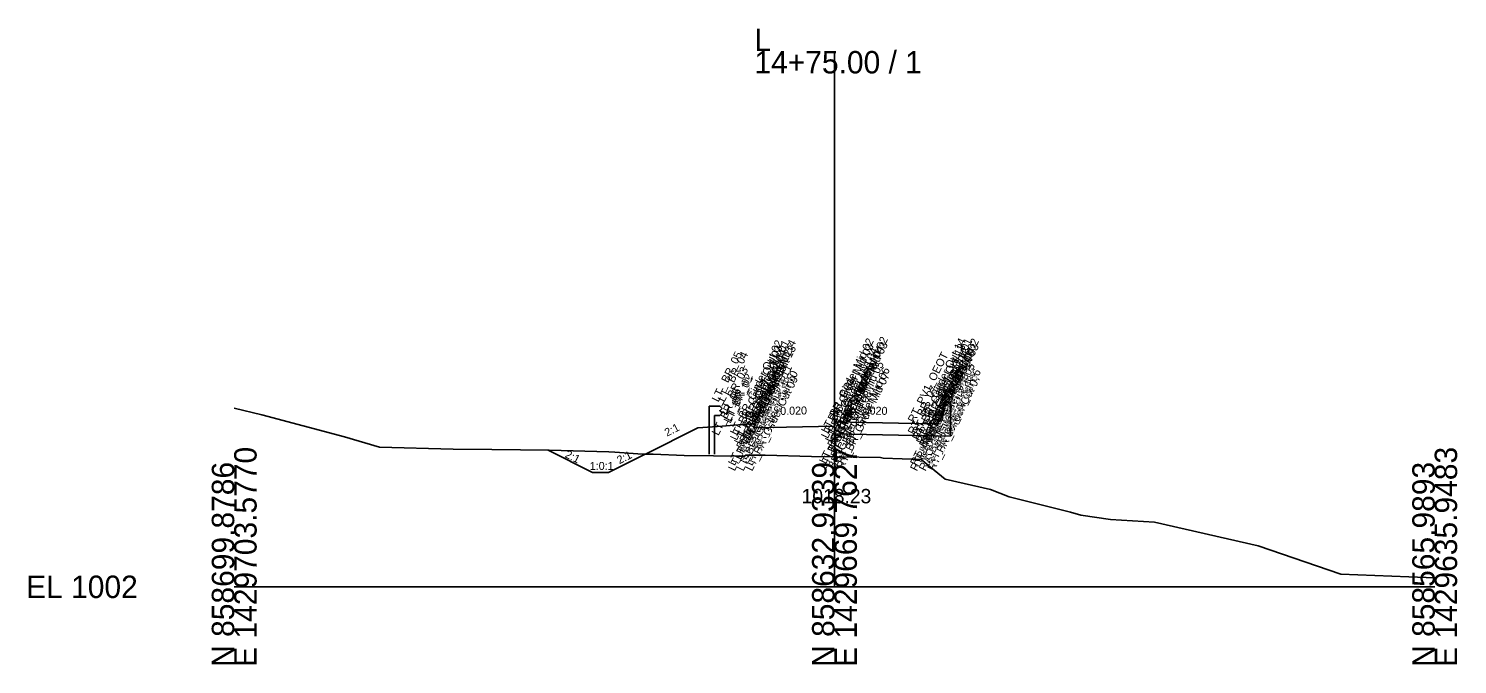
# Model space of a CAD drawing. Extents: x -26 to 176, y -10 to 13058.
# Drawn here: x -25.7 to 152.8, y 6490.3 to 6569.7 of the extents above; entities that cross this region are included whole.
import ezdxf

# ---------------------------------------------------------------- set-up
doc = ezdxf.new("R2010")
doc.units = 0
for name, color, linetype in [('Default', 7, 'Continuous'), ('Exist Cross Section Cell', 7, 'Continuous'), ('Exist XS Center Line Elevation Label', 7, 'Continuous'), ('Exist XS Ground Line', 7, 'Continuous'), ('Old_Level_50', 7, 'Continuous'), ('Prop CMT Concrete Structures', 7, 'Continuous'), ('Prop CMT Guardrail Graphics', 7, 'Continuous'), ('Prop CMT Pvmt Course 1', 7, 'Continuous'), ('Prop CMT Pvmt Surface Shoulder', 7, 'Continuous'), ('Prop CMT Shld Paved Course 1', 7, 'Continuous'), ('Prop CMT Slope Grass', 7, 'Continuous'), ('Prop CMT Subgrade Earthwork', 7, 'Continuous'), ('Prop XS Dump Level', 7, 'Continuous'), ('Prop XS SE Text', 7, 'Continuous'), ('Prop XS Side Slope Text', 7, 'Continuous')]:
    doc.layers.add(name, color=color, linetype=linetype)

msp = doc.modelspace()

# ---------------------------------------------------------------- linework, layer by layer
at = {"layer": 'Exist Cross Section Cell'}
for p, q in [((75, 6500), (75, 6566.93)), ((0, 6500), (75, 6500)), ((75, 6500), (150, 6500))]:
    msp.add_line(p, q, dxfattribs=at)
at = {"layer": 'Exist XS Ground Line'}
msp.add_lwpolyline([(0, 6522.31), (3.44, 6521.49), (13.79, 6518.72), (18.17, 6517.45), (27.35, 6517.18), (32.2, 6517.15), (39.36, 6517.05), (46.79, 6516.88), (47.56, 6516.84), (51.03, 6516.57), (52.33, 6516.56), (56.24, 6516.42), (59.9, 6516.38), (62.96, 6516.34), (63.78, 6516.33), (63.92, 6516.46), (66.35, 6516.43), (72.14, 6516.29), (75, 6516.23), (75.38, 6516.22), (80.77, 6516.15), (81.07, 6516.09), (85.84, 6515.89), (88.82, 6513.45), (94.51, 6512.15), (96.84, 6511.22), (104.48, 6509.34), (105.79, 6508.93), (109.51, 6508.39), (114.97, 6508.07), (127.95, 6505.12), (138.29, 6501.59), (146.77, 6501.25), (150, 6501.11)], dxfattribs=at)
at = {"layer": 'Old_Level_50'}
for points in [[(63.78, 6516.33), (63.92, 6516.46), (66.35, 6516.43), (72.14, 6516.29), (75, 6516.23), (75, 6520.07), (65, 6519.87), (65, 6520.41), (60.95, 6520.08), (57.95, 6519.84), (51.39, 6516.57), (52.33, 6516.56), (56.24, 6516.42), (59.9, 6516.38), (62.96, 6516.34)], [(51.39, 6516.57), (52.33, 6516.56), (56.24, 6516.42), (59.9, 6516.38), (62.96, 6516.34), (63.78, 6516.33), (63.92, 6516.46), (66.35, 6516.43), (72.14, 6516.29), (75, 6516.23), (75, 6520.07), (65, 6519.87), (65, 6520.41), (60.95, 6520.08), (57.95, 6519.84)], [(51.03, 6516.57), (51.37, 6516.57), (46.78, 6514.27), (44.78, 6514.27), (39.22, 6517.05), (39.36, 6517.05), (46.79, 6516.88), (47.56, 6516.84)], [(51.03, 6516.57), (51.37, 6516.57), (46.78, 6514.27), (44.78, 6514.27), (39.22, 6517.05), (39.36, 6517.05), (46.79, 6516.88), (47.56, 6516.84)]]:
    msp.add_lwpolyline(points, close=True, dxfattribs=at)
at = {"layer": 'Prop CMT Concrete Structures'}
for points in [[(75, 6520.61), (85, 6520.41), (88, 6520.35), (88.01, 6520.6), (88.59, 6521.43), (88.76, 6523.01), (89.5, 6523.01), (89.5, 6518.82)], [(75, 6519.11), (75, 6520.61)], [(75, 6519.11), (75, 6520.61)], [(89.5, 6518.82), (85, 6518.91), (75, 6519.11)]]:
    msp.add_lwpolyline(points, dxfattribs=at)
at = {"layer": 'Prop CMT Guardrail Graphics'}
for points in [[(59.34, 6516.58), (59.34, 6522.58)], [(59.34, 6522.58), (60.68, 6522.58), (60.95, 6522.29)], [(60.95, 6522.29), (60.68, 6522)], [(60.68, 6522), (60.95, 6521.71)], [(60.95, 6521.71), (60.68, 6521.42), (60.01, 6521.42)], [(60.01, 6521.42), (60.01, 6516.58)]]:
    msp.add_lwpolyline(points, dxfattribs=at)
at = {"layer": 'Prop CMT Pvmt Course 1'}
for points in [[(65, 6520.41), (65, 6519.87)], [(75, 6516.23), (75, 6520.07)]]:
    msp.add_lwpolyline(points, dxfattribs=at)
at = {"layer": 'Prop CMT Pvmt Surface Shoulder'}
msp.add_lwpolyline([(65, 6520.41), (65, 6520.41)], dxfattribs=at)
at = {"layer": 'Prop CMT Shld Paved Course 1'}
for points in [[(65, 6520.41), (65, 6520.41)], [(65, 6519.87), (65, 6520.41)]]:
    msp.add_lwpolyline(points, dxfattribs=at)
at = {"layer": 'Prop CMT Slope Grass'}
for p, q in [((44.78, 6514.27), (39.22, 6517.05)), ((46.78, 6514.27), (51.37, 6516.57)), ((46.78, 6514.27), (44.78, 6514.27))]:
    msp.add_line(p, q, dxfattribs=at)
for points in [[(60.95, 6520.08), (57.95, 6519.84)], [(65, 6520.41), (60.95, 6520.08)], [(57.95, 6519.84), (51.39, 6516.57)]]:
    msp.add_lwpolyline(points, dxfattribs=at)
at = {"layer": 'Prop CMT Subgrade Earthwork'}
msp.add_lwpolyline([(75, 6520.07), (65, 6519.87)], dxfattribs=at)

# ---------------------------------------------------------------- texts
at = {"layer": 'Default'}
msp.add_text('-', height=0.0001, dxfattribs=at).set_placement((0, 6500))
at = {"layer": 'Exist Cross Section Cell'}
for s, p in [('L', (65, 6566.93)), ('14+75.00 / 1', (65, 6564.13)), ('EL 1002', (-26, 6498.6))]:
    msp.add_text(s, height=2.8, dxfattribs=at).set_placement(p)
for s, p in [('E 1429703.5770', (2.8, 6490)), ('E 1429669.7627', (77.8, 6490)), ('E 1429635.9483', (152.8, 6490)), ('N 858699.8786', (0, 6490)), ('N 858632.9339', (75, 6490)), ('N 858565.9893', (150, 6490))]:
    msp.add_text(s, height=2.8, rotation=90, dxfattribs=at).set_placement(p)
at = {"layer": 'Exist XS Center Line Elevation Label'}
msp.add_text('1018.23', height=1.8, dxfattribs=at).set_placement((70.9, 6510.43))
msp.add_text('1018.23', height=1.8, dxfattribs=at).set_placement((70.9, 6510.43))
msp.add_text('1018.23', height=1.8, dxfattribs=at).set_placement((70.9, 6510.43))
at = {"layer": 'Prop XS Dump Level'}
for s, p in [('LT_BR_Girder Out 02', (62.79, 6518.86)), ('LT_BR_Girder Out 14', (64.46, 6518.9)), ('LT_BR_Girder Mid 02', (74.17, 6519.09)), ('RT_BR_Girder Mid 02', (75.83, 6519.09)), ('RT_BR_Girder Out 14', (85.54, 6518.9)), ('RT_BR_Girder Out 01', (86.38, 6518.88)), ('RT_BR_Girder Out 02', (87.21, 6518.86)), ('LT_ BR_05', (60.5, 6523.01)), ('LT_ BR_04', (61.24, 6523.01)), ('LT_BR_Girder Out 03', (62.79, 6518.21)), ('LT_BR_Girder Out 04', (63.29, 6517.71)), ('LT_BR_Girder Out 01', (63.62, 6518.88)), ('LT_BR_Girder Out 12', (63.96, 6517.71)), ('LT_BR_Girder Out 13', (64.46, 6518.21)), ('LT_PV1_OEOT', (65, 6520.41)), ('LT_BR_Girder Mid 03', (74.17, 6518.44)), ('LT_BR_Girder Mid 04', (74.67, 6517.94)), ('RT_BR_Girder Mid 04', (75.33, 6517.94)), ('RT_BR_Girder Mid 03', (75.83, 6518.44)), ('RT_PV1_OEOT', (85, 6520.41)), ('RT_BR_Girder Out 13', (85.54, 6518.21)), ('RT_BR_Girder Out 12', (86.04, 6517.71)), ('RT_BR_Girder Out 04', (86.71, 6517.71)), ('RT_BR_Girder Out 03', (87.21, 6518.21)), ('RT_ BR_04', (88.76, 6523.01)), ('RT_ BR_05', (89.5, 6523.01)), ('LT_BR_03', (61.41, 6521.43)), ('LT_BR_Girder Out 05', (63.29, 6515.8)), ('LT_BR_Girder Out 11', (63.96, 6515.8)), ('LT_BR_Girder Mid 06', (73.92, 6515.27)), ('LT_BR_Girder Mid 05', (74.67, 6516.02)), ('RT_BR_Girder Mid 05', (75.33, 6516.02)), ('RT_BR_Girder Mid 06', (76.08, 6515.27)), ('RT_BR_Girder Out 10', (85.29, 6515.05)), ('RT_BR_Girder Out 11', (86.04, 6515.8)), ('RT_BR_Girder Out 05', (86.71, 6515.8)), ('RT_BR_Girder Out 06', (87.46, 6515.05)), ('RT_BR_03', (88.59, 6521.43)), ('LT_BR_02', (61.99, 6520.6)), ('LT_BR_01', (62, 6520.35)), ('LT_BR_Girder Out 06', (62.54, 6515.05)), ('LT_BR_Girder Out 07', (62.54, 6514.38)), ('LT_BR_Girder Out 08', (63.62, 6514.38)), ('LT_BR_Girder Out 10', (64.71, 6515.05)), ('LT_BR_Girder Out 09', (64.71, 6514.38)), ('LT_BR_Girder Mid 07', (73.92, 6514.61)), ('PV1_PGL', (75, 6520.61)), ('RT_BR_Girder Mid 07', (76.08, 6514.61)), ('RT_BR_Girder Out 09', (85.29, 6514.38)), ('RT_BR_Girder Out 08', (86.38, 6514.38)), ('RT_BR_Girder Out 07', (87.46, 6514.38)), ('RT_BR_01', (88, 6520.35)), ('RT_BR_02', (88.01, 6520.6)), ('LT_BR_06', (60.5, 6518.82)), ('LT_BR_07', (65, 6518.91)), ('BR_Girder Mid 08', (75, 6514.61)), ('BR_PGL', (75, 6519.11)), ('RT_BR_07', (85, 6518.91)), ('RT_BR_06', (89.5, 6518.82))]:
    msp.add_text(s, height=1, rotation=63.5833, dxfattribs=at).set_placement(p)
at = {"layer": 'Prop XS SE Text'}
for rotation, p in [(1.1458, (68.23, 6521.47)), (1.1458, (68.23, 6521.47)), (358.8542, (78.27, 6521.54))]:
    msp.add_text('0.020', height=1, rotation=rotation, dxfattribs=at).set_placement(p)
at = {"layer": 'Prop XS Side Slope Text'}
for rotation, p in [(26.5651, (54.08, 6518.75)), (333.4349, (41.24, 6516.22)), (26.5651, (48.13, 6515.3))]:
    msp.add_text('2:1', height=1, rotation=rotation, dxfattribs=at).set_placement(p)
msp.add_text('1:0:1', height=1, dxfattribs=at).set_placement((44.43, 6514.6))

doc.saveas('drawing.dxf')
